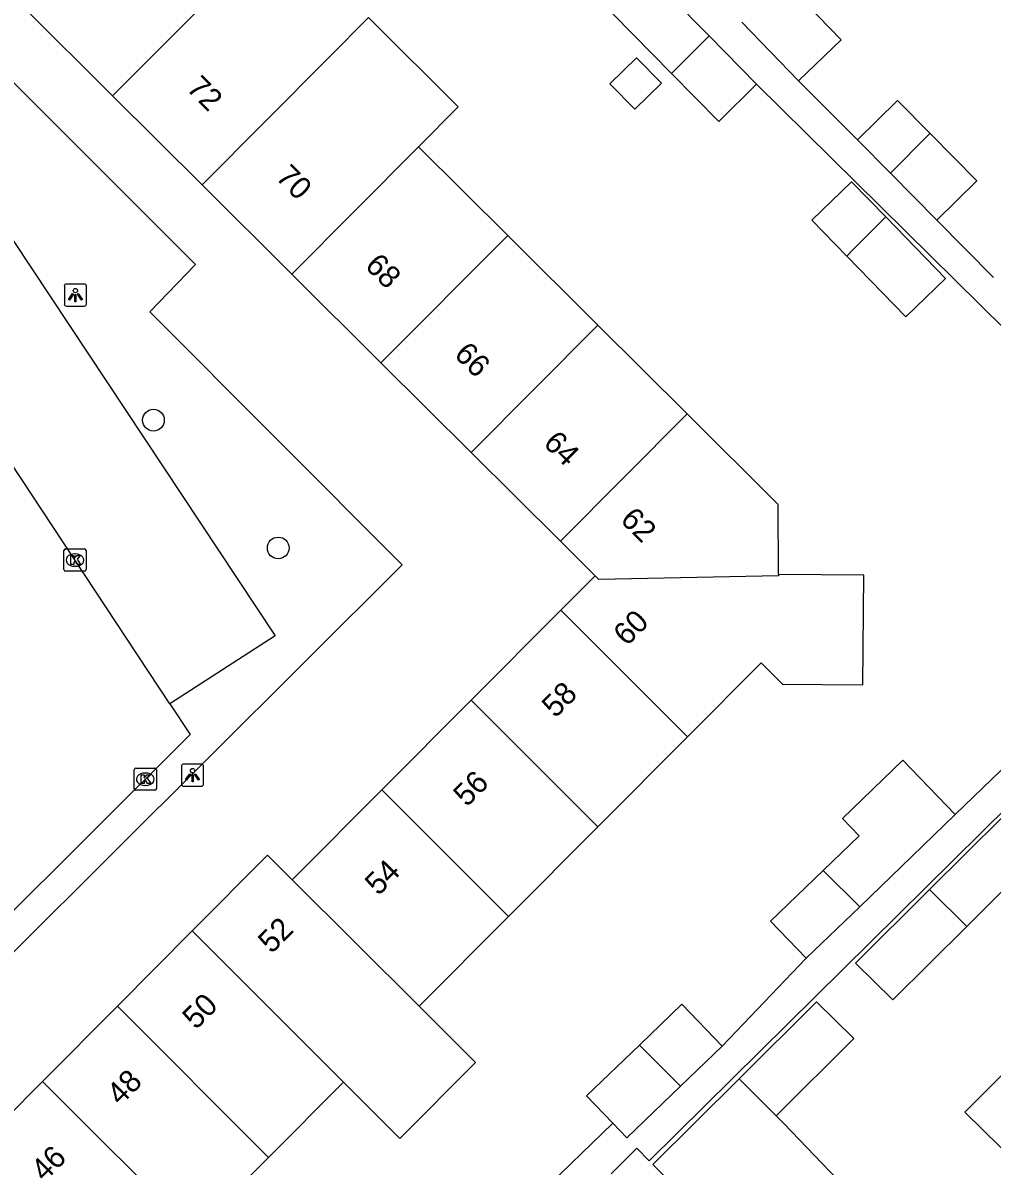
# Model space of a CAD drawing. Extents: x 159961 to 160856, y 382704 to 383353.
# Drawn here: x 160241.5 to 160285.2, y 383117.7 to 383169.2 of the extents above; entities that cross this region are included whole.
import ezdxf

# ---------------------------------------------------------------- set-up
doc = ezdxf.new("R2010")
doc.units = 0
for name, color, linetype in [('IMGEO_Boom', 7, 'Continuous'), ('IMGEO_Kolk', 7, 'Continuous'), ('IMGEO_Lichtpunt', 7, 'Continuous'), ('IMGEO_Pand', 7, 'Continuous'), ('IMGEO_Pand_nummerreeks', 7, 'Continuous'), ('IMGEO_Rijbaan_lokaal_open', 7, 'Continuous'), ('IMGEO_Voetpad_open', 7, 'Continuous')]:
    doc.layers.add(name, color=color, linetype=linetype)

msp = doc.modelspace()

# ---------------------------------------------------------------- linework, layer by layer
at = {"layer": 'IMGEO_Boom'}
for centre in [(160247.425, 383151.325), (160253.04, 383145.569)]:
    msp.add_circle(centre, 0.489, dxfattribs=at)
at = {"layer": 'IMGEO_Kolk'}
for p, q in [((160243.466, 383145.524), (160244.318, 383145.524)), ((160243.391, 383144.598), (160243.391, 383145.45)), ((160243.879, 383145.304), (160243.904, 383145.304)), ((160244.392, 383145.45), (160244.392, 383144.598)), ((160244.318, 383144.524), (160243.466, 383144.524)), ((160243.902, 383144.744), (160243.877, 383144.744)), ((160246.556, 383134.73), (160246.556, 383135.582)), ((160246.631, 383135.656), (160247.483, 383135.656)), ((160247.044, 383135.436), (160247.069, 383135.436)), ((160247.557, 383135.582), (160247.557, 383134.73)), ((160247.483, 383134.656), (160246.631, 383134.656)), ((160247.067, 383134.876), (160247.042, 383134.876))]:
    msp.add_line(p, q, dxfattribs=at)
for points in [[(160243.466, 383145.524), (160244.318, 383145.524)], [(160243.391, 383144.598), (160243.391, 383145.45)], [(160243.712, 383145.224), (160243.835, 383145.224), (160243.835, 383145.073), (160243.965, 383145.224), (160244.129, 383145.224), (160243.983, 383145.073), (160244.136, 383144.824), (160243.984, 383144.824), (160243.899, 383144.988), (160243.835, 383144.921), (160243.835, 383144.824), (160243.712, 383144.824), (160243.712, 383145.224)], [(160244.392, 383145.45), (160244.392, 383144.598)], [(160244.318, 383144.524), (160243.466, 383144.524)], [(160246.556, 383134.73), (160246.556, 383135.582)], [(160246.631, 383135.656), (160247.483, 383135.656)], [(160246.877, 383135.356), (160247, 383135.356), (160247, 383135.205), (160247.13, 383135.356), (160247.294, 383135.356), (160247.148, 383135.205), (160247.301, 383134.956), (160247.149, 383134.956), (160247.064, 383135.12), (160247, 383135.053), (160247, 383134.956), (160246.877, 383134.956), (160246.877, 383135.356)], [(160247.557, 383135.582), (160247.557, 383134.73)], [(160247.483, 383134.656), (160246.631, 383134.656)]]:
    msp.add_lwpolyline(points, dxfattribs=at)
for centre, start, end in [((160243.468, 383145.448), 91.552, 178.448), ((160243.468, 383145.448), 91.552, 178.448), ((160244.316, 383145.448), 1.552, 88.448), ((160244.316, 383145.448), 1.552, 88.448), ((160243.468, 383144.6), 181.552, 268.448), ((160243.468, 383144.6), 181.552, 268.448), ((160244.316, 383144.6), 271.552, 358.448), ((160244.316, 383144.6), 271.552, 358.448), ((160246.633, 383135.58), 91.552, 178.448), ((160246.633, 383135.58), 91.552, 178.448), ((160247.481, 383135.58), 1.552, 88.448), ((160247.481, 383135.58), 1.552, 88.448), ((160246.633, 383134.732), 181.552, 268.448), ((160246.633, 383134.732), 181.552, 268.448), ((160247.481, 383134.732), 271.552, 358.448), ((160247.481, 383134.732), 271.552, 358.448)]:
    msp.add_arc(centre, 0.0765, start, end, dxfattribs=at)
for centre, major_axis, ratio, start_param, end_param in [((160243.878, 383145.024), (-0.387, 0.002), 0.722429, 4.712389, 7.853982), ((160243.903, 383145.024), (-0.39, 0.002), 0.717154, 1.570796, 4.712389), ((160247.043, 383135.156), (-0.387, 0.002), 0.722429, 4.712389, 7.853982), ((160247.068, 383135.156), (-0.39, 0.002), 0.717154, 1.570796, 4.712389)]:
    msp.add_ellipse(centre, major_axis=major_axis, ratio=ratio, start_param=start_param, end_param=end_param, dxfattribs=at)
at = {"layer": 'IMGEO_Lichtpunt'}
for p, q in [((160243.413, 383157.362), (160243.413, 383156.555)), ((160243.413, 383157.362), (160243.413, 383156.555)), ((160244.315, 383157.457), (160243.507, 383157.457)), ((160244.315, 383157.457), (160243.507, 383157.457)), ((160244.409, 383156.555), (160244.409, 383157.362)), ((160244.409, 383156.555), (160244.409, 383157.362)), ((160243.507, 383156.461), (160244.315, 383156.461)), ((160243.507, 383156.461), (160244.315, 383156.461)), ((160248.685, 383135.742), (160248.685, 383134.935)), ((160248.685, 383135.742), (160248.685, 383134.935)), ((160249.587, 383135.837), (160248.779, 383135.837)), ((160249.587, 383135.837), (160248.779, 383135.837)), ((160249.681, 383134.935), (160249.681, 383135.742)), ((160249.681, 383134.935), (160249.681, 383135.742)), ((160248.779, 383134.841), (160249.587, 383134.841)), ((160248.779, 383134.841), (160249.587, 383134.841))]:
    msp.add_line(p, q, dxfattribs=at)
for points in [[(160243.787, 383157.026), (160243.826, 383156.998), (160243.638, 383156.736), (160243.6, 383156.763), (160243.787, 383157.026)], [(160243.889, 383156.978), (160243.936, 383156.978), (160243.936, 383156.656), (160243.889, 383156.656), (160243.889, 383156.978)], [(160243.999, 383156.998), (160244.037, 383157.025), (160244.224, 383156.763), (160244.185, 383156.735), (160243.999, 383156.998)], [(160249.059, 383135.406), (160249.098, 383135.378), (160248.91, 383135.116), (160248.872, 383135.143), (160249.059, 383135.406)], [(160249.161, 383135.358), (160249.208, 383135.358), (160249.208, 383135.036), (160249.161, 383135.036), (160249.161, 383135.358)], [(160249.271, 383135.378), (160249.309, 383135.405), (160249.496, 383135.143), (160249.457, 383135.115), (160249.271, 383135.378)]]:
    msp.add_lwpolyline(points, dxfattribs=at)
for centre in [(160243.912, 383157.16), (160249.184, 383135.54)]:
    msp.add_circle(centre, 0.0994, dxfattribs=at)
for centre, start, end in [((160243.507, 383157.362), 90, 180), ((160243.507, 383157.362), 90, 180), ((160244.315, 383157.362), 0, 90), ((160244.315, 383157.362), 0, 90), ((160243.507, 383156.555), 180, 270), ((160243.507, 383156.555), 180, 270), ((160244.315, 383156.555), 270, 0), ((160244.315, 383156.555), 270, 360), ((160248.779, 383135.742), 90, 180), ((160248.779, 383135.742), 90, 180), ((160249.587, 383135.742), 0, 90), ((160249.587, 383135.742), 0, 90), ((160248.779, 383134.935), 180, 270), ((160248.779, 383134.935), 180, 270), ((160249.587, 383134.935), 270, 0), ((160249.587, 383134.935), 270, 360)]:
    msp.add_arc(centre, 0.0946, start, end, dxfattribs=at)
at = {"layer": 'IMGEO_Pand'}
for points in [[(160270.751, 383166.941), (160267.248, 383170.51), (160268.949, 383172.18)], [(160272.434, 383168.63), (160268.949, 383172.18)], [(160251.27, 383171.69), (160251.293, 383171.667), (160245.586, 383165.929)], [(160275.799, 383171.132), (160278.379, 383168.46), (160276.466, 383166.613)], [(160241.547, 383169.948), (160245.586, 383165.929)], [(160257.229, 383169.335), (160257.106, 383169.457), (160255.319, 383167.661), (160249.611, 383161.924)], [(160259.358, 383163.642), (160261.146, 383165.438), (160257.229, 383169.335)], [(160276.466, 383166.613), (160273.917, 383169.253)], [(160270.751, 383166.941), (160272.434, 383168.63)], [(160274.571, 383166.453), (160272.434, 383168.63)], [(160267.972, 383166.469), (160269.167, 383167.642), (160270.288, 383166.5), (160269.093, 383165.327), (160267.972, 383166.469)], [(160274.571, 383166.453), (160272.87, 383164.782), (160270.751, 383166.941)], [(160245.586, 383165.929), (160249.611, 383161.924)], [(160279.117, 383163.951), (160280.915, 383165.726), (160282.383, 383164.238)], [(160282.383, 383164.238), (160282.349, 383164.205), (160280.6, 383162.448)], [(160282.69, 383160.33), (160284.489, 383162.104), (160282.383, 383164.238)], [(160253.649, 383157.906), (160259.358, 383163.642)], [(160259.358, 383163.642), (160263.377, 383159.643)], [(160280.6, 383162.448), (160279.117, 383163.951)], [(160278.632, 383158.716), (160277.062, 383160.33), (160278.845, 383162.066), (160280.39, 383160.478)], [(160280.6, 383162.448), (160282.69, 383160.33)], [(160249.611, 383161.924), (160253.649, 383157.906)], [(160280.39, 383160.478), (160283.083, 383157.712), (160281.299, 383155.976), (160278.632, 383158.716)], [(160280.39, 383160.478), (160278.909, 383158.99), (160278.632, 383158.716)], [(160263.377, 383159.643), (160257.667, 383153.908)], [(160263.377, 383159.643), (160267.43, 383155.61)], [(160257.667, 383153.908), (160253.649, 383157.906)], [(160267.43, 383155.61), (160261.721, 383149.875)], [(160267.43, 383155.61), (160271.456, 383151.604)], [(160261.721, 383149.875), (160257.667, 383153.908)], [(160271.456, 383151.604), (160265.746, 383145.87)], [(160275.555, 383144.38), (160275.547, 383147.534), (160271.456, 383151.604)], [(160265.746, 383145.87), (160261.721, 383149.875)], [(160265.746, 383145.87), (160267.301, 383144.322)], [(160267.301, 383144.322), (160265.761, 383142.775)], [(160275.555, 383144.38), (160275.555, 383144.319), (160267.477, 383144.144), (160267.301, 383144.322)], [(160271.462, 383137.072), (160274.777, 383140.403), (160275.747, 383139.437), (160279.352, 383139.4), (160279.403, 383144.34), (160275.555, 383144.38)], [(160261.725, 383138.718), (160265.761, 383142.775)], [(160265.761, 383142.775), (160271.462, 383137.072)], [(160257.702, 383134.676), (160261.725, 383138.718)], [(160267.425, 383133.015), (160261.725, 383138.718)], [(160271.462, 383137.072), (160267.425, 383133.015)], [(160277.564, 383131.048), (160279.184, 383132.609), (160278.435, 383133.386), (160281.158, 383136.01), (160283.519, 383133.562)], [(160253.675, 383130.628), (160253.82, 383130.774), (160257.702, 383134.676)], [(160263.403, 383128.972), (160257.702, 383134.676)], [(160283.519, 383133.562), (160281.095, 383131.224), (160279.219, 383129.415)], [(160284.034, 383128.529), (160287.304, 383131.781), (160285.631, 383133.437), (160282.359, 383130.183)], [(160267.425, 383133.015), (160263.403, 383128.972)], [(160253.675, 383130.628), (160252.565, 383131.737), (160249.168, 383128.323)], [(160276.812, 383127.095), (160275.198, 383128.768), (160277.564, 383131.048)], [(160277.564, 383131.048), (160279.219, 383129.415)], [(160259.38, 383124.929), (160253.675, 383130.628)], [(160282.359, 383130.183), (160279.025, 383126.867), (160280.704, 383125.218), (160284.034, 383128.529)], [(160282.359, 383130.183), (160284.034, 383128.529)], [(160279.219, 383129.415), (160276.812, 383127.095)], [(160263.403, 383128.972), (160259.38, 383124.929)], [(160245.8, 383124.938), (160249.168, 383128.323)], [(160249.168, 383128.323), (160255.979, 383121.511)], [(160242.424, 383121.545), (160245.8, 383124.938)], [(160245.8, 383124.938), (160252.606, 383118.121)], [(160255.979, 383121.511), (160258.513, 383118.977), (160261.916, 383122.396), (160259.38, 383124.929)], [(160269.296, 383123.183), (160271.204, 383125.023), (160273.019, 383123.141)], [(160275.456, 383119.999), (160278.953, 383123.477), (160277.274, 383125.126), (160273.786, 383121.657)], [(160286.382, 383117.768), (160283.949, 383120.158), (160288.206, 383124.411), (160290.633, 383122.016)], [(160268.11, 383119.661), (160266.921, 383120.894), (160269.296, 383123.183)], [(160271.148, 383121.338), (160270.896, 383121.59), (160269.296, 383123.183)], [(160273.019, 383123.141), (160271.148, 383121.338)], [(160239.034, 383118.139), (160242.424, 383121.545)], [(160249.24, 383114.738), (160242.424, 383121.545)], [(160255.979, 383121.511), (160252.606, 383118.121)], [(160271.148, 383121.338), (160268.736, 383119.012), (160268.11, 383119.661)], [(160273.786, 383121.657), (160269.905, 383117.798), (160270.092, 383117.609), (160275.082, 383112.566), (160278.927, 383116.397), (160275.806, 383119.652), (160275.456, 383119.999)], [(160275.456, 383119.999), (160273.984, 383121.461), (160273.786, 383121.657)], [(160252.606, 383118.121), (160249.24, 383114.738)]]:
    msp.add_lwpolyline(points, dxfattribs=at)
at = {"layer": 'IMGEO_Rijbaan_lokaal_open'}
for points in [[(160248.169, 383138.549), (160231.381, 383163.97)], [(160248.169, 383138.549), (160249.08, 383137.169), (160240.216, 383128.341), (160224.465, 383112.653)]]:
    msp.add_lwpolyline(points, dxfattribs=at)
at = {"layer": 'IMGEO_Voetpad_open'}
for points in [[(160230.53, 383168.138), (160235.985, 383171.674), (160249.323, 383158.33), (160247.254, 383156.197), (160258.623, 383144.806), (160241.159, 383127.393), (160211.6, 383097.92), (160215.213, 383094.199)], [(160232.71, 383164.856), (160236.028, 383167.066), (160252.9, 383141.612), (160248.169, 383138.549)], [(160279.117, 383163.951), (160276.466, 383166.613)], [(160283.519, 383133.562), (160295.852, 383145.458), (160274.571, 383166.453)], [(160285.234, 383157.752), (160283.977, 383159.026), (160282.69, 383160.33)], [(160268.029, 383117.389), (160269.177, 383118.534), (160269.731, 383117.974), (160299.647, 383147.532), (160312.955, 383133.845)], [(160273.019, 383123.141), (160276.812, 383127.095)], [(160264.818, 383116.486), (160268.11, 383119.661)]]:
    msp.add_lwpolyline(points, dxfattribs=at)

# ---------------------------------------------------------------- texts
at = {"layer": 'IMGEO_Pand_nummerreeks'}
for s, rotation, p in [('72', 315.1431, (160248.863, 383166.222)), ('70', 315.1431, (160252.883, 383162.222)), ('68', 315.1433, (160256.899, 383158.226)), ('66', 315.1433, (160260.913, 383154.232)), ('64', 315.1433, (160264.929, 383150.236)), ('62', 314.9942, (160268.391, 383146.793)), ('60', 45.1433, (160268.737, 383141.114)), ('58', 45.142, (160265.516, 383137.877)), ('56', 45.142, (160261.533, 383133.875)), ('54', 45.1433, (160257.553, 383129.875)), ('52', 45.1433, (160252.743, 383127.266)), ('50', 45.1425, (160249.339, 383123.844)), ('48', 45.1425, (160245.93, 383120.419)), ('46', 45.1425, (160242.52, 383116.991))]:
    msp.add_text(s, height=1, rotation=rotation, dxfattribs=at).set_placement(p)

doc.saveas('drawing.dxf')
